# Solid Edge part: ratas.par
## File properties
Author: Kalle
Template: Iso Part.par
Last saved by: Georg
Revision: 2
Application: Solid Edge
Accuracy: 0,990
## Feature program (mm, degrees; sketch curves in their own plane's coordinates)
sketch for "unnamed Protrusion 1" plane through (0, 0, 0) normal (0, -1, 0) x-axis (1, 0, 0)
  circle centre (28.8781, -26.601) radius 15
extrude "unnamed Protrusion 1" add finite 12 along +normal
sketch for "ExtrudedCutout_1" plane through (28.8781, -12, -26.601) normal (0, -1, 0) x-axis (1, 0, 0)
  circle centre (-0.0272, 0.1362) radius 10
extrude "ExtrudedCutout_1" cut finite 5 along -normal
sketch for "unnamed Cutout 1" plane through (28.8781, -12, -26.601) normal (0, -1, 0) x-axis (1, 0, 0)
extrude "unnamed Cutout 1" cut to key point along -normal
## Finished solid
Body 1: solid body, 6 faces, 6 edges, 0 vertices.
  Faces by surface: cylinder 3, plane 3
  Edges by curve: circle 6
Bounding box of the edges (mm): 30.000 x 12.000 x 30.000, from (13.8781, -12, -41.601) to (43.8781, 0, -11.601).
Cylindrical faces by radius (mm): R4 x1, R10 x1, R15 x1
Planar faces by outward normal: +y 1, -y 2
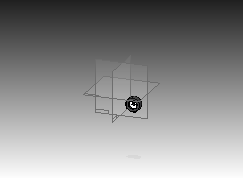
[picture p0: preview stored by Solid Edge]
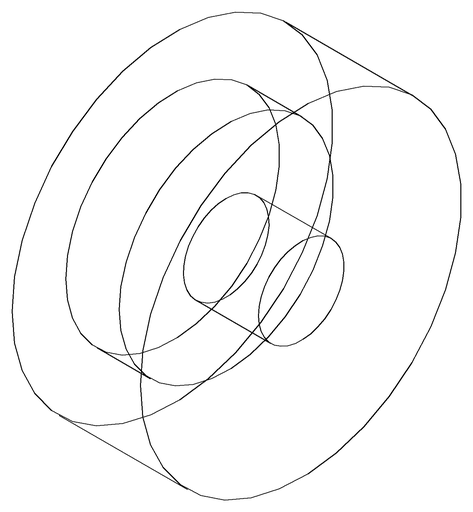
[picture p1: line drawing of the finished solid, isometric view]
